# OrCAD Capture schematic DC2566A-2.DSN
size Custom; note: 3-20 GHz MICROWAVE MIXER
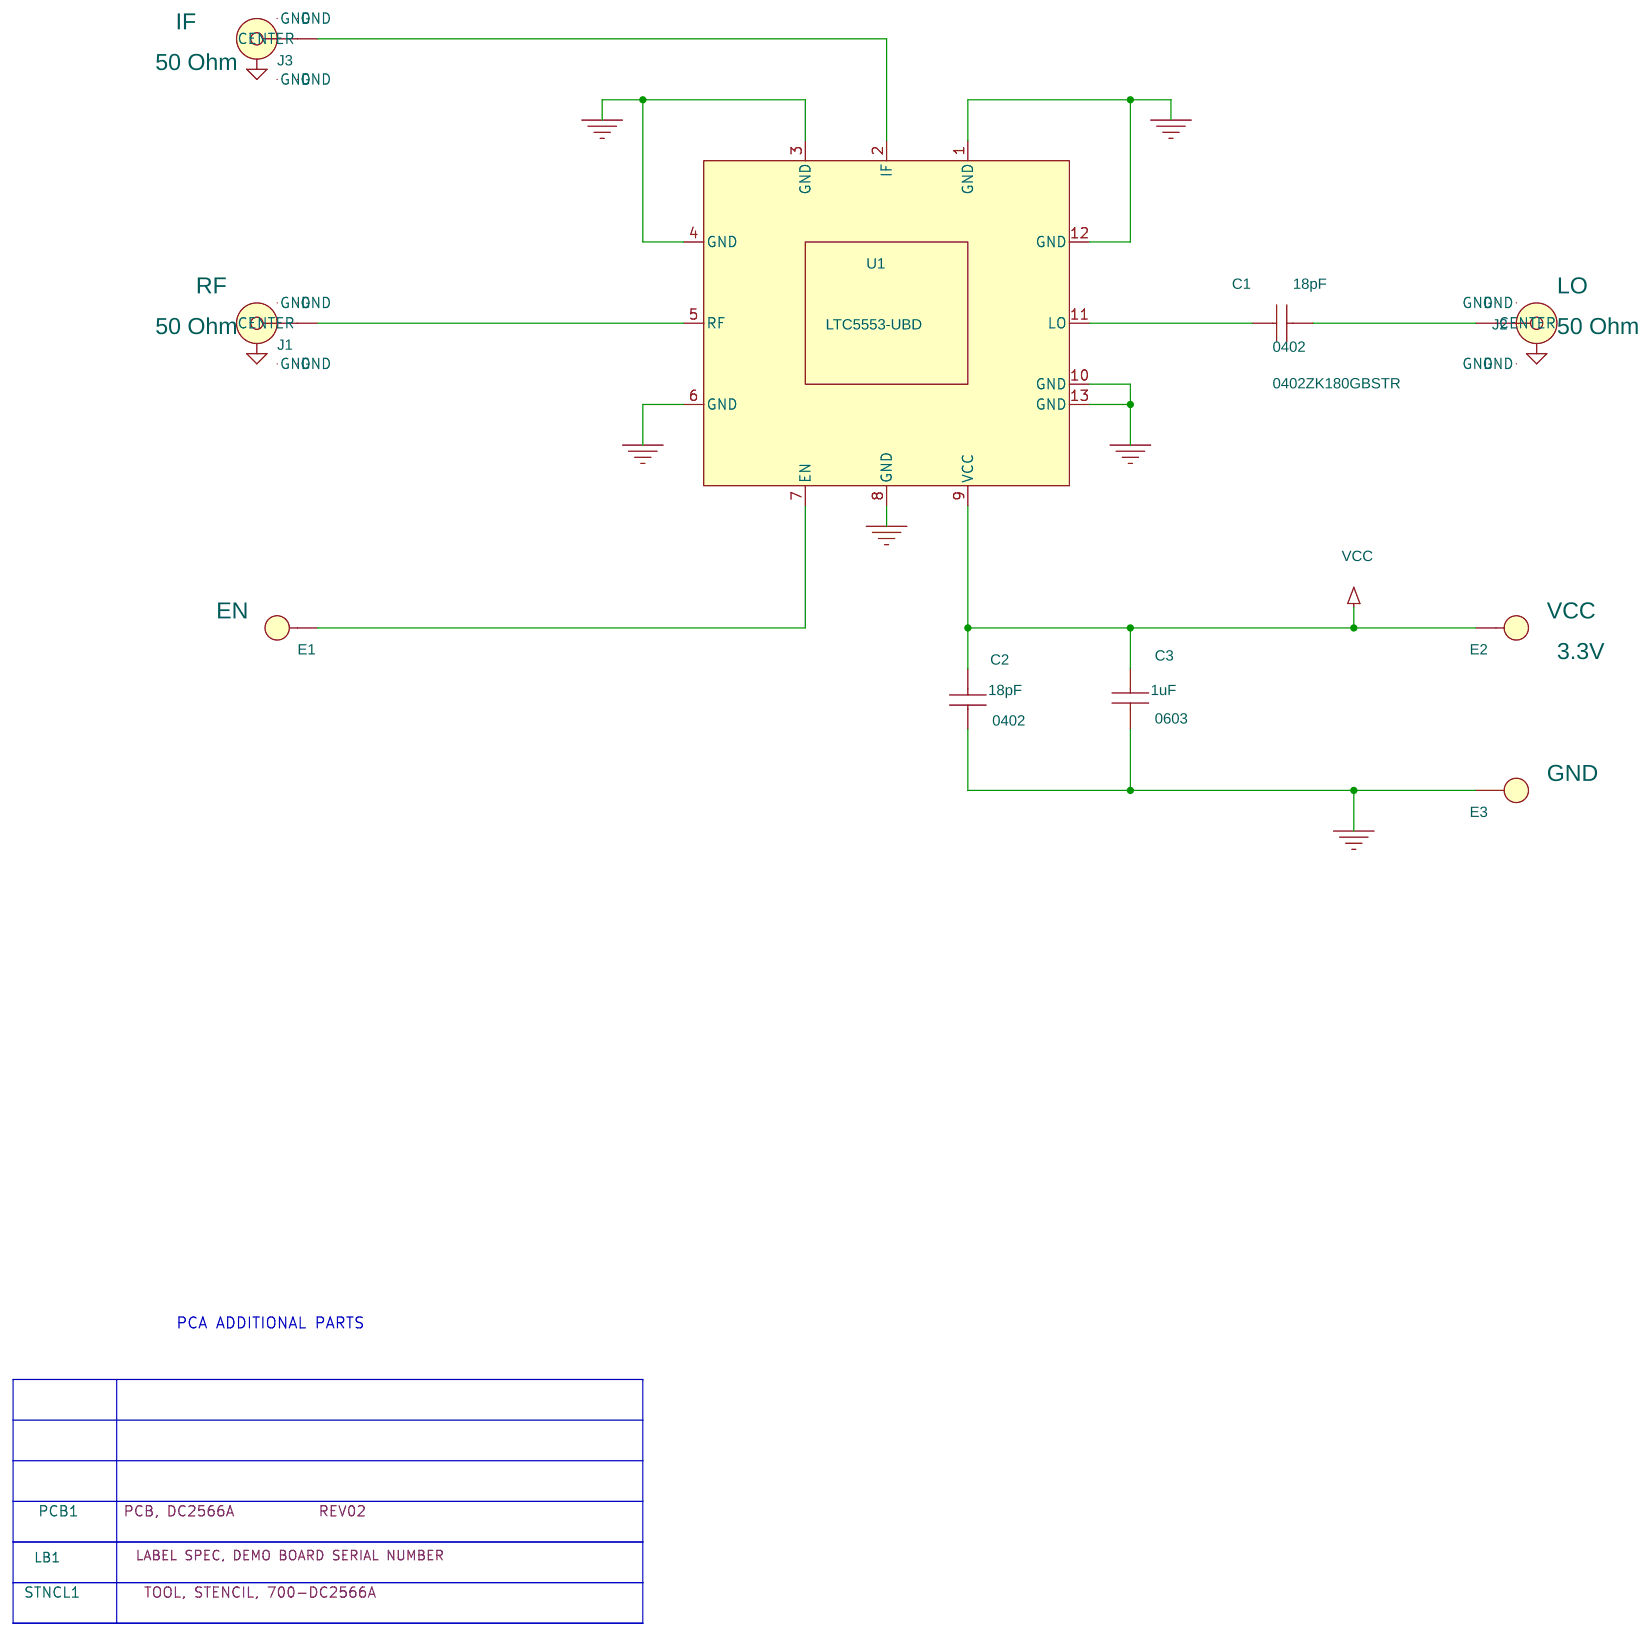
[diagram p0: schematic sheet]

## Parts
C1  18pF  [CC0402N]
C2  18pF  [CC0402N]
C3  1uF  [CC0603N]
E1  TEST POINT  [MILLMAX2308]
E2  TEST POINT  [MILLMAX2308]
E3  TEST POINT  [MILLMAX2308]
J1  SMA  [EMERSON_142-0761-881]
J2  SMA  [EMERSON_142-0761-881]
J3  SMA  [EMERSON_142-0701-851]
LB1  LABEL  [895-0154_REV01]
PCB1  PCB FABRICATION
STNCL1  TOOL, STENCIL, 700-DC2566A
U1  LTC5553-UBD  [LTC-UDB-12-1941]

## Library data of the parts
C1 = CAP: CAP.,18pF,10V,2%,0402,SINGLE SOURCE ONLY; CLASS: DISCRETE; FPLIST: CC0402N,CC0402L,CC0402M; Manufacturer: AVX; Manufacturer PN: 0402ZK180GBSTR; PART_NUMBER: 150-0575; Package Size: 0402; Rated Voltage: 10V; Tolerance: 2%; UserField01: SINGLE SOURCE ONLY
C2 = CAP: CAP.,18pF,C0G,50V,1%,0402,SINGLE SOURCE ONLY; CLASS: DISCRETE; Dielectric Type: C0G; FPLIST: CC0402N,CC0402L,CC0402M; Manufacturer: MURATA; Manufacturer PN: GJM1555C1H180FB01D; PART_NUMBER: 150-0556; Package Size: 0402; Rated Voltage: 50V; Tolerance: 1%; UserField01: SINGLE SOURCE ONLY
C3 = CAP: CAP.,1uF,X7R,10V,10%,0603,SINGLE SOURCE ONLY; CLASS: DISCRETE; Dielectric Type: X7R; FPLIST: CC0603N,CC0603L,CC0603M; Manufacturer: MURATA; Manufacturer PN: GRM188R71A105KA61D; PART_NUMBER: 150-0557; Package Size: 0603; Rated Voltage: 10V; Tolerance: 10%; UserField01: SINGLE SOURCE ONLY
E1 = TEST_POINT_.156_MILL-MAX_2308: TEST POINT,TURRET,0.064",MTG. HOLE; 1: EN; CLASS: IO; Manufacturer: MILL-MAX; Manufacturer PN: 2308-2-00-80-00-00-07-0; PART_NUMBER: 260-0004
E2 = TEST_POINT_.156_MILL-MAX_2308: TEST POINT,TURRET,0.064",MTG. HOLE; 1: VCC; 2: 3.3V; CLASS: IO; Manufacturer: MILL-MAX; Manufacturer PN: 2308-2-00-80-00-00-07-0; PART_NUMBER: 260-0004
E3 = TEST_POINT_.156_MILL-MAX_2308: TEST POINT,TURRET,0.064",MTG. HOLE; 1: GND; CLASS: IO; Manufacturer: MILL-MAX; Manufacturer PN: 2308-2-00-80-00-00-07-0; PART_NUMBER: 260-0004
J1 = CONN_SMA_5PIN: CONN.,SMA,RCP,13.48mm,THT RA; 1: RF; 2: 50 Ohm; CLASS: IO; Manufacturer: CINCH CONNECTIVITY SOLUTIONS; Manufacturer PN: 142-0761-881; PART_NUMBER: 250-0645
J2 = CONN_SMA_5PIN: CONN.,SMA,RCP,13.48mm,THT RA; 1: LO; 2: 50 Ohm; CLASS: IO; Manufacturer: CINCH CONNECTIVITY SOLUTIONS; Manufacturer PN: 142-0761-881; PART_NUMBER: 250-0645
J3 = CONN_SMA_5PIN: CONN.,SMA,JACK, RCPT,END LAUNCH, STR,50 OHMS; 1: IF; 2: 50 Ohm; CLASS: IO; Manufacturer: CINCH CONNECTIVITY SOLUTIONS; Manufacturer PN: 142-0701-851; PART_NUMBER: 250-0446
LB1 = BLANK_LABEL: LABEL SPEC, DEMO BOARD SERIAL NUMBER; Manufacturer: BRADY; Manufacturer PN: THT-96-717-10; PART_NUMBER: 895-0154
PCB1 = BLANK_PCB_PART: PCB, DC2566A; BOM Notes: REV02; CLASS: DISCRETE; Manufacturer: LINEAR TECHNOLOGY; Manufacturer PN: 600-DC2566A; PART_NUMBER: 600-DC2566A
STNCL1 = BLANK_STENCIL_PART: CLASS: DISCRETE; Manufacturer: LINEAR TECHNOLOGY; Manufacturer PN: 830-DC2566A; PART_NUMBER: 830-DC2566A
U1 = LTC5553-UDB: IC,4-18 GHz MICROWAVE MIXER,12-pin QFN; CLASS: IC; Manufacturer: LINEAR TECHNOLOGY; Manufacturer PN: LTC5553IUDB#PBF; PART_NUMBER: LTC5553IUDB#PBF; Package Type: 12-pin QFN

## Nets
GND: C2.1 C3.2 E3.1(A) J1.2(GND) J1.3(GND) J1.4(GND) J1.5(GND) J2.2(GND) J2.3(GND) J2.4(GND) J2.5(GND) J3.2(GND) J3.3(GND) J3.4(GND) J3.5(GND) U1.1(GND) U1.3(GND) U1.4(GND) U1.6(GND) U1.8(GND) U1.10(GND) U1.12(GND) U1.13(GND)
VCC: C2.2 C3.1 E2.1(A) U1.9(VCC)
N16911844: E1.1(A) U1.7(EN)
N16911857: J3.1(CENTER) U1.2(IF)
N16911937: J1.1(CENTER) U1.5(RF)
N16918792: C1.1 U1.11(LO)
N16935480: C1.2 J2.1(CENTER)

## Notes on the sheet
- PCA ADDITIONAL PARTS
